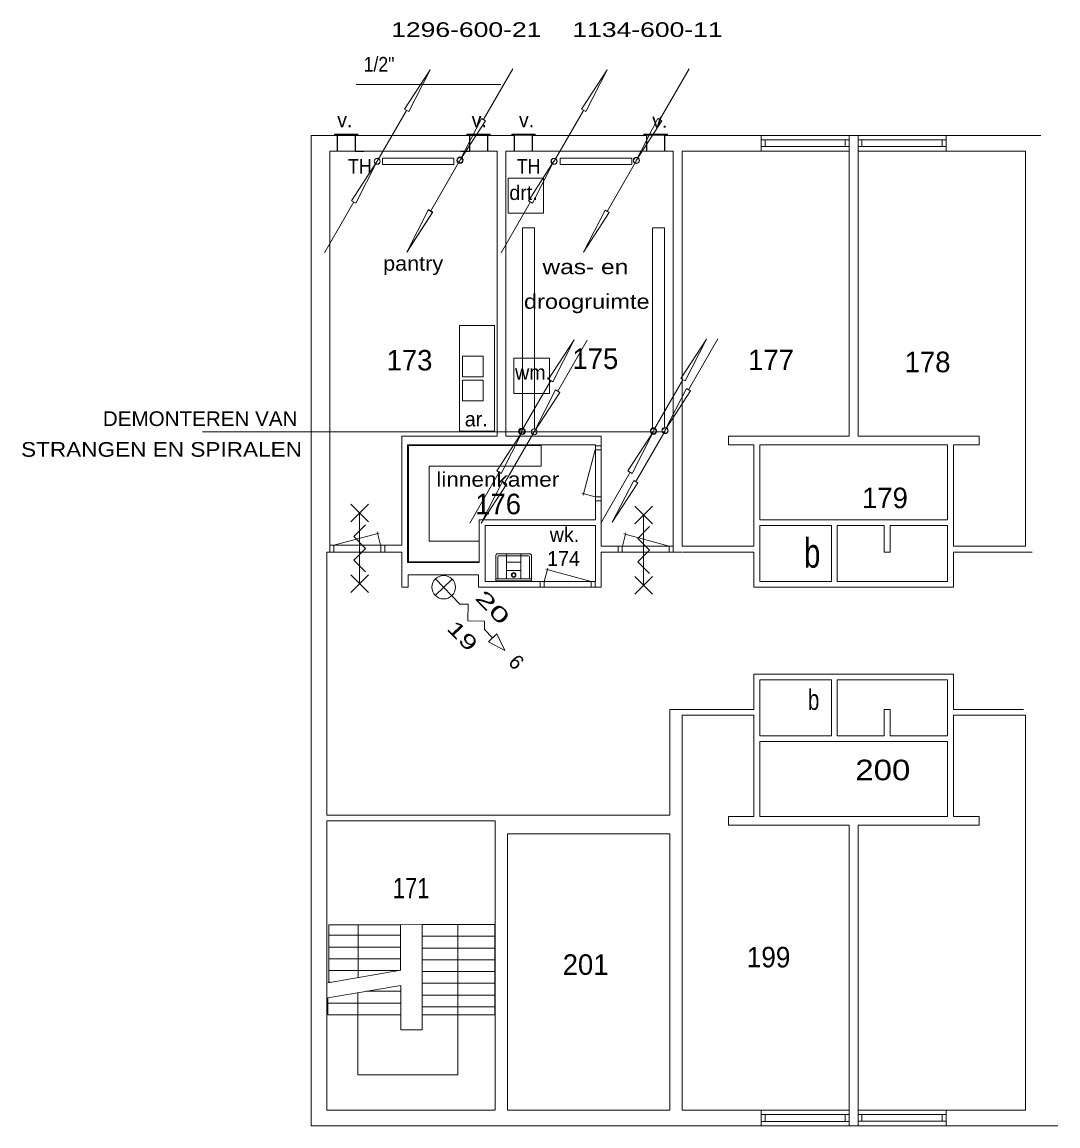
# Model space of a CAD drawing. Extents: x 295824 to 414724, y 24924 to 109024.
# Drawn here: x 340295 to 357941, y 62514 to 81314 of the extents above; entities that cross this region are included whole.
import ezdxf
from ezdxf.enums import TextEntityAlignment as Align

# ---------------------------------------------------------------- set-up
doc = ezdxf.new("R2010")
doc.units = 0
doc.header["$LTSCALE"] = 100
doc.layers.add('16', color=7, linetype='Continuous', lineweight=13)
doc.layers.add('61', color=7, linetype='Continuous', lineweight=13)

msp = doc.modelspace()

# ---------------------------------------------------------------- linework, layer by layer
at = {"layer": '16'}
for p, q in [((348654.7, 80518.3), (348154.7, 79652.3)), ((351658.9, 80518.3), (351158.9, 79652.3)), ((348450.1, 80249), (345985, 80249)), ((346345.4, 78944.3), (346845.4, 79810.3)), ((349361.4, 78944.3), (349861.4, 79810.3)), ((347757.3, 78967.3), (347257.3, 78101.3)), ((347751.4, 78955.5), (347251.4, 78089.5)), ((350761.5, 78955.5), (350261.5, 78089.5)), ((345445.8, 77383.8), (345945.8, 78249.8)), ((348456, 77383.8), (348956, 78249.8)), ((349920.1, 75894.7), (349420.1, 75028.7)), ((352147.2, 75918.5), (351647.2, 75052.5)), ((348801.6, 74344.5), (349301.6, 75210.5)), ((351052.5, 74356.4), (351552.5, 75222.4)), ((343368.4, 74337.8), (351252.5, 74337.8)), ((349017.9, 74336.4), (348517.9, 73470.4)), ((351249.9, 74353.1), (350749.9, 73487.1)), ((347920.8, 72782), (348420.8, 73648)), ((350152.8, 72782), (350652.8, 73648))]:
    msp.add_line(p, q, dxfattribs=at)
for points in [[(347245.4, 80503.3), (346881.4, 79789.3), (346809.4, 79831.3)], [(350261.4, 80503.3), (349897.4, 79789.3), (349825.4, 79831.3)], [(347754.7, 78959.3), (348118.7, 79673.3), (348190.7, 79631.3)], [(350758.9, 78959.3), (351122.9, 79673.3), (351194.9, 79631.3)], [(346435.4, 78890.1), (347652.1, 78890.1), (347652.1, 78997.3), (346435.4, 78997.3)], [(349463.1, 78890.1), (350679.8, 78890.1), (350679.8, 78997.3), (349463.1, 78997.3)], [(346345.8, 78942.8), (345981.8, 78228.8), (345909.8, 78270.8)], [(349356, 78942.8), (348992, 78228.8), (348920, 78270.8)], [(346851.4, 77396.5), (347215.4, 78110.5), (347287.4, 78068.5)], [(346857.3, 77408.3), (347221.3, 78122.3), (347293.3, 78080.3)], [(349861.5, 77396.5), (350225.5, 78110.5), (350297.5, 78068.5)], [(349701.6, 75903.5), (349337.6, 75189.5), (349265.6, 75231.5)], [(351952.5, 75915.4), (351588.5, 75201.4), (351516.5, 75243.4)], [(349020.1, 74335.7), (349384.1, 75049.7), (349456.1, 75007.7)], [(351247.2, 74359.5), (351611.2, 75073.5), (351683.2, 75031.5)], [(348820.8, 74341), (348456.8, 73627), (348384.8, 73669)], [(351052.8, 74341), (350688.8, 73627), (350616.8, 73669)], [(348117.9, 72777.4), (348481.9, 73491.4), (348553.9, 73449.4)], [(350349.9, 72794.1), (350713.9, 73508.1), (350785.9, 73466.1)]]:
    msp.add_lwpolyline(points, close=True, dxfattribs=at)
for points in [[(348821.9, 74378.4), (348821.9, 77810.4), (349024.4, 77810.4), (349024.4, 74390.3)], [(351037.1, 74378.4), (351037.1, 77810.4), (351239.5, 77810.4), (351239.5, 74390.3)]]:
    msp.add_lwpolyline(points, dxfattribs=at)
for centre in [(346345.4, 78944), (346345.8, 78942.5), (347751.4, 78955.8), (347754.7, 78959.6), (347757.3, 78967.6), (349356, 78942.5), (349361.4, 78944), (350758.9, 78959.6), (350761.5, 78955.8), (348801.6, 74344.2), (348820.8, 74340.7), (349017.9, 74336.7), (349020.1, 74336), (351052.5, 74356.1), (351052.8, 74340.7), (351247.2, 74359.8), (351249.9, 74353.4)]:
    msp.add_circle(centre, 50, dxfattribs=at)
at = {"layer": '61'}
for p, q in [((345217.1, 79383.2), (345217.1, 62513.8)), ((345587.1, 79383.2), (345217.1, 79383.2)), ((345217.1, 79383.2), (348680.6, 79383.2)), ((346016.7, 79402.3), (345618.4, 79402.3)), ((345618.4, 79402.3), (345618.4, 79387.1)), ((346016.7, 79387.1), (345618.4, 79387.1)), ((345663.2, 79380.8), (345663.2, 79112.1)), ((345668.7, 79387.1), (345668.7, 79112.8)), ((345967.4, 79387.1), (345967.4, 79112.8)), ((345973.9, 79380.8), (345973.9, 79112.3)), ((346016.7, 79402.3), (346016.7, 79387.1)), ((348270.4, 79402.3), (347872.1, 79402.3)), ((347872.1, 79402.3), (347872.1, 79387.1)), ((348270.4, 79387.1), (347872.1, 79387.1)), ((347916.9, 79380.8), (347916.9, 79112.3)), ((347922.4, 79387.1), (347922.4, 79112.8)), ((348221.1, 79387.1), (348221.1, 79112.8)), ((348227.6, 79380.8), (348227.6, 79110.8)), ((348270.4, 79402.3), (348270.4, 79387.1)), ((349034.2, 79404.7), (348635.9, 79404.7)), ((348635.9, 79404.7), (348635.9, 79389.6)), ((349034.2, 79389.6), (348635.9, 79389.6)), ((348680.6, 79383.2), (348680.6, 79114.5)), ((348686.2, 79389.6), (348686.2, 79115.2)), ((348984.9, 79389.6), (348984.9, 79115.2)), ((348991.3, 79383.2), (348991.3, 79114.8)), ((348991.3, 79383.2), (350934.3, 79383.2)), ((349034.2, 79404.7), (349034.2, 79389.6)), ((351287.9, 79404.7), (350889.6, 79404.7)), ((350889.6, 79404.7), (350889.6, 79389.6)), ((351287.9, 79389.6), (350889.6, 79389.6)), ((350934.3, 79383.2), (350934.3, 79114.8)), ((350939.9, 79389.6), (350939.9, 79115.2)), ((351238.6, 79389.6), (351238.6, 79115.2)), ((351245, 79383.2), (351245, 79113.2)), ((351245, 79383.2), (357647.5, 79383.2)), ((351287.9, 79404.7), (351287.9, 79389.6)), ((352887, 79116.2), (352887, 79386.2)), ((356035, 79116.2), (356035, 79386.4)), ((352953.8, 79194.5), (352953.8, 79308.4)), ((354318.8, 79193.9), (354318.8, 79307.9)), ((354602.3, 79194.8), (354602.3, 79308.8)), ((355966.6, 79194.5), (355966.6, 79308.2)), ((345537.1, 72288.4), (345537.1, 79113.2)), ((345967.4, 79112.8), (345668.7, 79112.8)), ((345973.9, 79112.3), (346119.6, 79112.3)), ((347770.2, 79112.3), (347916.9, 79112.3)), ((348221.1, 79112.8), (347922.4, 79112.8)), ((348537.1, 79114.5), (348680.6, 79114.5)), ((351387.1, 79113.2), (348537.1, 79113.2)), ((348984.9, 79115.2), (348686.2, 79115.2)), ((348991.3, 79114.8), (349137.1, 79114.8)), ((350787.6, 79114.8), (350934.3, 79114.8)), ((351238.6, 79115.2), (350939.9, 79115.2)), ((351537.1, 79113.2), (354387.1, 79113.2)), ((357387.1, 79113.2), (354537.1, 79113.2)), ((347797.2, 75624.9), (348147.2, 75624.9)), ((348148.1, 75623.2), (348148.1, 75273.2)), ((348147.2, 75270.8), (347797.2, 75270.8)), ((347797.2, 75216.7), (348147.2, 75216.7)), ((348148.1, 75215), (348148.1, 74865)), ((348147.2, 74862.6), (347797.2, 74862.6)), ((346862.1, 72108.2), (346862.1, 74113.2)), ((350161.6, 74095.2), (350060.7, 74095.2)), ((350160, 74095.2), (350063.3, 74095.2)), ((350060.1, 74029), (349853, 73256.2)), ((350159.5, 74028.2), (350062, 74028.2)), ((350059.5, 73230.6), (349832.6, 73291.3)), ((350159.3, 73228.2), (350060.7, 73228.2)), ((350159.5, 73161.2), (350060.7, 73161.2)), ((346195.9, 73100.6), (345895.9, 72800.6)), ((345895.9, 73100.6), (346195.9, 72800.6)), ((346045.9, 71750.6), (346045.9, 72950.6)), ((351032.1, 73071), (350732.1, 72771)), ((350732.1, 73071), (351032.1, 72771)), ((350882.1, 71721), (350882.1, 72921)), ((345605.3, 72403), (346378, 72610.1)), ((346403.7, 72403.7), (346342.9, 72630.5)), ((350521.2, 72389.3), (350582, 72616.2)), ((351319.7, 72388.7), (350546.9, 72595.7)), ((345606, 72288.4), (345606, 72402.4)), ((346406, 72288.4), (346406, 72402.4)), ((346473, 72288.4), (346473, 72402.4)), ((350451.9, 72289.2), (350451.9, 72388.1)), ((350518.9, 72289.4), (350518.9, 72388.1)), ((351318.9, 72289.2), (351318.9, 72388.1)), ((351385.9, 72289.2), (351385.9, 72388.1)), ((345487.1, 72288.4), (345537.1, 72288.4)), ((346762.1, 71688.2), (346762.1, 72288.4)), ((348363.9, 72222.4), (348363.9, 71807.4)), ((348938.9, 72257.4), (348398.9, 72257.4)), ((348398.9, 71847.4), (348398.9, 72207.4)), ((348413.9, 72222.4), (348923.9, 72222.4)), ((348548.9, 71832.4), (348548.9, 72257.4)), ((348788.9, 71832.4), (348788.9, 72257.4)), ((348938.9, 72207.4), (348938.9, 71847.4)), ((348973.9, 71807.4), (348973.9, 72222.4)), ((350162.1, 72288.2), (350162.1, 71688.2)), ((351533.2, 72288.2), (350162.1, 72288.2)), ((352762.1, 72288.2), (351548.3, 72288.2)), ((348082.1, 72108.2), (346862.1, 72108.2)), ((348788.9, 72115.7), (348548.9, 72115.7)), ((349191.5, 71788.3), (349252.3, 72015.2)), ((346195.9, 71900.6), (345895.9, 71600.6)), ((345895.9, 71900.6), (346195.9, 71600.6)), ((348072.1, 71898.2), (346872.1, 71898.2)), ((346872.1, 71688.2), (346872.1, 71898.2)), ((347620.7, 71827.9), (347333, 71550.1)), ((348072.1, 71688.2), (348072.1, 71898.2)), ((348963.9, 71832.4), (348373.9, 71832.4)), ((348788.9, 71974), (348548.9, 71974)), ((349989.9, 71787.7), (349217.2, 71994.7)), ((351032.1, 71871), (350732.1, 71571)), ((350732.1, 71871), (351032.1, 71571)), ((346872.1, 71688.2), (346762.1, 71688.2)), ((350162.1, 71688.2), (348072.1, 71688.2)), ((348373.9, 71797.4), (348963.9, 71797.4)), ((349122.2, 71688.2), (349122.2, 71787.1)), ((349189.2, 71688.4), (349189.2, 71787.1)), ((349989.2, 71688.2), (349989.2, 71787.1)), ((350056.2, 71688.2), (350056.2, 71787.1)), ((346021.2, 65040.9), (346021.2, 65937.7)), ((346742.6, 65937.7), (347108.3, 65943.1)), ((348348.2, 65943.1), (347108.3, 65943.1)), ((345519.8, 65760.2), (346742.6, 65760.2)), ((348348.2, 65743.1), (347108.3, 65743.1)), ((345519.8, 65560.2), (346742.6, 65560.2)), ((348348.2, 65543.1), (347108.3, 65543.1)), ((345519.8, 65360.2), (346742.6, 65360.2)), ((348348.2, 65343.1), (347108.3, 65343.1)), ((346744.6, 65164.1), (345504.8, 64952.9)), ((345519.8, 65160.2), (346721.4, 65160.2)), ((348348.2, 65143.1), (347108.3, 65143.1)), ((346744.6, 64907.5), (345504.8, 64696.3)), ((345519.8, 64960.2), (345547.3, 64960.2)), ((345519.8, 64960.2), (345547.3, 64960.2)), ((348348.2, 64943.1), (347108.3, 64943.1)), ((345504.8, 64696.3), (345504.8, 64406.7)), ((346152.9, 64806.7), (346744.6, 64806.7)), ((348348.2, 64743.1), (347108.3, 64743.1)), ((345504.8, 64606.7), (346744.6, 64606.7)), ((348348.2, 64543.1), (347108.3, 64543.1)), ((345504.8, 64406.7), (346744.6, 64406.7)), ((346744.6, 64406.7), (346744.6, 64148.8)), ((347108.3, 64406.7), (347108.3, 64148.8)), ((347108.3, 64148.8), (346744.6, 64148.8)), ((351537.1, 62783.8), (354387.1, 62783.8)), ((352887, 62513.6), (352887, 62783.6)), ((352953.8, 62591.9), (352953.8, 62705.7)), ((354318.8, 62591.2), (354318.8, 62705.2)), ((357387.1, 62783.8), (354537.1, 62783.8)), ((354602.3, 62592.2), (354602.3, 62706.2)), ((355966.6, 62591.9), (355966.6, 62705.6)), ((356035, 62513.6), (356035, 62783.8)), ((357940.9, 62513.8), (345217.1, 62513.8))]:
    msp.add_line(p, q, dxfattribs=at)
for points in [[(354387.1, 79383.2), (354387.1, 74263.2), (352327.1, 74263.2), (352327.1, 74113.2), (352762.1, 74113.2), (352762.1, 72388.2), (351537.1, 72388.2), (351537.1, 79113.2)], [(354537.1, 79383.2), (354537.1, 74263.2), (356597.1, 74263.2), (356597.1, 74113.2), (356162.1, 74113.2), (356162.1, 72388.2), (357387.1, 72388.2), (357387.1, 79113.2)], [(345537.1, 79113.2), (348387.1, 79113.2), (348387.1, 74263.2), (346762.1, 74263.2), (346762.1, 72402.4)], [(349137.1, 74263.2), (348537.1, 74263.2), (348537.1, 79113.2)], [(348537.1, 74263.2), (350162.1, 74263.2), (350162.1, 72388.2), (351387.1, 72388.2), (351387.1, 79113.2)], [(351245, 79113.2), (351387.1, 79113.2), (351387.1, 77938.2)], [(347749, 74344.9), (348343.7, 74344.9), (348343.7, 76144.9)], [(347749, 74344.9), (347749, 76144.9), (348343.7, 76144.9)], [(347798.1, 75273.2), (347798.1, 75623.2), (347797.2, 75624.9)], [(347798.1, 74865), (347798.1, 75215), (347797.2, 75216.7)], [(346862.1, 74113.2), (350062.1, 74113.2), (350062.1, 72838.2), (348082.1, 72838.2), (348082.1, 72108.2)], [(346145.9, 71950.6), (345945.9, 72150.6), (346145.9, 72350.6), (345945.9, 72550.6), (346145.9, 72750.6)], [(350982.1, 71921), (350782.1, 72121), (350982.1, 72321), (350782.1, 72521), (350982.1, 72721)], [(345539, 72288.4), (345539, 72402.4), (346762.1, 72402.4)], [(346762.1, 72288.4), (345539, 72288.4), (345539, 72402.4)], [(345487.1, 72288.4), (345487.1, 67808.8), (351327.1, 67808.8), (351327.1, 69608.8)], [(357500.8, 72288.2), (356162.1, 72288.2), (356162.1, 71688.2), (352762.1, 71688.2), (352762.1, 72288.2)], [(347337.9, 71832.9), (347754.7, 71401.3), (347896.1, 71398.8), (347891.2, 71116), (348174, 71111.1), (348171.5, 70969.7), (348310.5, 70825.8)], [(351327.1, 69608.8), (352762.1, 69608.8), (352762.1, 70208.8), (356162.1, 70208.8), (356162.1, 69608.8), (357354.1, 69608.8)], [(354387.1, 62516), (354387.1, 67633.8), (352327.1, 67633.8), (352327.1, 67783.8), (352762.1, 67783.8), (352762.1, 69508.8), (351537.1, 69508.8), (351537.1, 62783.8)], [(354537.1, 62513.8), (354537.1, 67633.8), (356597.1, 67633.8), (356597.1, 67783.8), (356162.1, 67783.8), (356162.1, 69508.8), (357387.1, 69508.8), (357387.1, 62783.8)], [(346742.6, 65163.8), (346742.6, 65937.7), (345519.8, 65937.7), (345519.8, 64960.2)], [(347720, 65943.1), (347720, 63382.5), (346017.2, 63382.5), (346017.2, 64783.6)], [(345504.8, 64406.7), (346744.6, 64406.7), (346744.6, 64907.5)]]:
    msp.add_lwpolyline(points, dxfattribs=at)
for points in [[(352887, 79194.4), (352887, 79308.4), (354385.6, 79308.4), (354385.6, 79194.4)], [(354537.2, 79194.5), (354537.2, 79308.5), (356036.6, 79308.5), (356036.6, 79194.5)], [(348575.8, 78057.6), (348575.8, 78657.6), (349180.3, 78657.6), (349180.3, 78057.6)], [(348674.1, 74989), (348674.1, 75589), (349278.6, 75589), (349278.6, 74989)], [(346890.8, 74100.9), (349138, 74100.9), (349138, 73750.9), (347232.4, 73750.9), (347232.4, 72473.7), (348080, 72473.7), (348080, 72123.7), (346878.5, 72123.7), (346878.5, 74100.9)], [(352862.1, 74113.2), (356062.1, 74113.2), (356062.1, 72838.2), (352862.1, 72838.2)], [(348182.1, 72738.2), (350062.1, 72738.2), (350062.1, 71788.2), (348182.1, 71788.2)], [(352862.1, 72738.2), (354082.1, 72738.2), (354082.1, 71788.2), (352862.1, 71788.2)], [(354182.1, 72738.2), (354982.1, 72738.2), (354982.1, 72288.2), (355082.1, 72288.2), (355082.1, 72738.2), (356062.1, 72738.2), (356062.1, 71788.2), (354182.1, 71788.2)], [(348238.5, 70756.3), (348382.4, 70895.2), (348518.9, 70610)], [(352862.1, 69158.8), (354082.1, 69158.8), (354082.1, 70108.8), (352862.1, 70108.8)], [(354182.1, 69158.8), (354982.1, 69158.8), (354982.1, 69608.8), (355082.1, 69608.8), (355082.1, 69158.8), (356062.1, 69158.8), (356062.1, 70108.8), (354182.1, 70108.8)], [(352862.1, 67783.8), (356062.1, 67783.8), (356062.1, 69058.8), (352862.1, 69058.8)], [(345487.1, 67708.8), (348357.1, 67708.8), (348357.1, 62783.8), (345487.1, 62783.8)], [(348567.1, 67488.8), (351327.1, 67488.8), (351327.1, 62783.8), (348567.1, 62783.8)], [(347108.3, 64406.7), (348348.2, 64406.7), (348348.2, 65943.1), (347108.3, 65943.1)], [(352887, 62591.7), (352887, 62705.7), (354385.6, 62705.7), (354385.6, 62591.7)], [(354536, 62591.9), (354536, 62705.9), (356035.3, 62705.9), (356035.3, 62591.9)]]:
    msp.add_lwpolyline(points, close=True, dxfattribs=at)
for centre, radius in [((347476.9, 71689), 200), ((348668.9, 71897.4), 40), ((348668.9, 71897.4), 30)]:
    msp.add_circle(centre, radius, dxfattribs=at)
for centre, radius, start, end in [((348398.9, 72222.4), 35, 90, 180), ((348413.9, 72207.4), 15, 90, 180), ((348923.9, 72207.4), 15, 0, 90), ((348938.9, 72222.4), 35, 0, 90), ((348373.9, 71822.4), 10, 90, 180), ((348413.9, 71847.4), 15, 180, 270), ((348923.9, 71847.4), 15, 270, 0), ((348963.9, 71822.4), 10, 0, 90), ((348373.9, 71807.4), 10, 180, 270), ((348963.9, 71807.4), 10, 270, 0)]:
    msp.add_arc(centre, radius, start, end, dxfattribs=at)

# ---------------------------------------------------------------- texts
at = {"layer": '16'}
for s, width, p in [('1296-600-21', 1.35, (346582.6, 81060.4)), ('1134-600-11', 1.35, (349669.3, 81060.4)), ('1/2"', 0.9, (346113.5, 80470.5)), ('TH', 0.9, (345849, 78734)), ('TH', 0.9, (348723.7, 78734)), ('DEMONTEREN VAN', 1.05, (341671.2, 74434.7)), ('STRANGEN EN SPIRALEN', 1.15, (340277.8, 73910.3))]:
    msp.add_text(s, height=250, dxfattribs=dict(at, width=width)).set_placement(p)
at = {"layer": '61'}
for s, p in [('v.', (345663.2, 79523.1)), ('v.', (347953.3, 79523.1)), ('v.', (348759.2, 79523.1)), ('v.', (351028.5, 79513)), ('drt.', (348595.5, 78283.9)), ('wm.', (348693.8, 75222.7)), ('ar.', (347837.4, 74427.3)), ('wk.', (349284.1, 72460.1))]:
    msp.add_text(s, height=250, dxfattribs=at).set_placement(p)
for s, width, p in [('pantry', 1.1, (346446.1, 77079.2)), ('was- en', 1.25, (349159.5, 77020.4)), ('droogruimte', 1.2, (348845, 76430.2)), ('linnenkamer', 1.15, (347352, 73400.5))]:
    msp.add_text(s, height=250, dxfattribs=dict(at, width=width)).set_placement(p)
for s, height, p in [('173', 350, (346895, 75380.1)), ('175', 350, (350061.3, 75405.8)), ('177', 350, (353053.9, 75385.6)), ('178', 350, (355720.1, 75350.2)), ('179', 350, (354994.5, 73035.2)), ('176', 350, (348404.6, 72931.6)), ('174', 250, (349519.4, 72052.8)), ('201', 350, (349894.9, 65086.8))]:
    msp.add_text(s, height=height, dxfattribs=at).set_placement(p, align=Align.CENTER)
for s, height, width, p in [('b', 500, 0.75, (353755.1, 72022.7)), ('b', 350, 0.75, (353779.2, 69598.2)), ('200', 350, 1.2, (354957.5, 68401.1)), ('171', 350, 0.8, (346923.2, 66388.8)), ('199', 350, 0.95, (353012.2, 65213.6))]:
    msp.add_text(s, height=height, dxfattribs=dict(at, width=width)).set_placement(p, align=Align.CENTER)
for s, width, p in [('20', 1.75, (347996.1, 71494.7)), ('19', 1.5, (347514.7, 70974.6))]:
    msp.add_text(s, height=250, rotation=314, dxfattribs=dict(at, width=width)).set_placement(p)
msp.add_text('6', height=250, rotation=314, dxfattribs=at).set_placement((348561, 70394.7))

doc.saveas('drawing.dxf')
